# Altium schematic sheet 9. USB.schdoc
size 297 x 209 mm; Symbol: Drawing-Symbol_A4; Company: 嘉立创EDA; Version: V1.0; Page Size: A4; @Project Name: 西柚在学EtherCAT; @Update Date: 2026-07-29; @Create Date: 2026-07-29; Device: Drawing-Symbol_A4; @Board Name: HPM5E3YIVK1; @Page Name: P8; @Create Time: 01:19:22; @Page Count: 8; @Page No: 8; @Schematic Name: HPM5E3YIVK1; @Update Time: 01:19:22; @Assembly Variant: Basic; Border: 1; Title Block Position: 3; Size: A4; Width: 1170; Height: 825; Region Start: 1; X Region Count: 6; Y Region Count: 4; Blade Width: 10
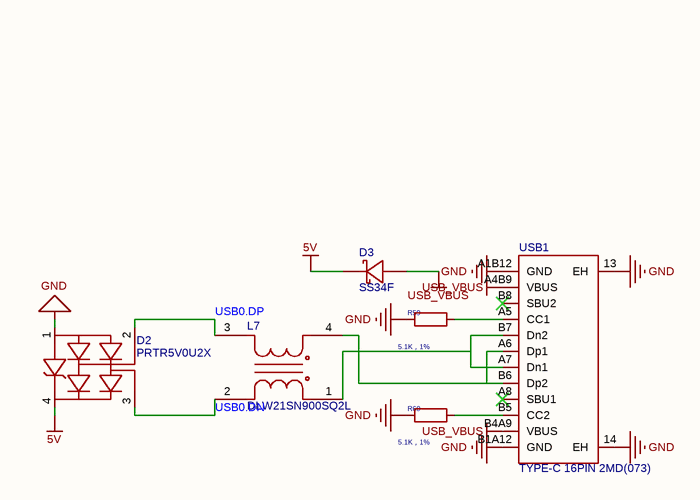
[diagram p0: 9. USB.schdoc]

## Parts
D2  PRTR5V0U2X  [SOT-143-4_L2.9-W1.3-P1.92-LS2.4-BL]
D3  SS34F  [SMAF_L3.5-W2.6-LS4.7-RD-1]
L7  DLW21SN900SQ2L  [FILTER-SMD_4P-L2.0-W1.2-BL_DLW21H]
R59  value 5.1K，1%  [02_HPM_Resistor:R_0402_1005Metric]
R60  value 5.1K，1%  [02_HPM_Resistor:R_0402_1005Metric]
USB1  TYPE-C 16PIN 2MD(073)  [USB-C-SMD_TYPE-C-16PIN-2MD-073]

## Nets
5V: D2.4 D3.1(K)
GND: D2.1 R59.1 R60.1 USB1.13(EH) USB1.14(EH) USB1.A1B12(GND) USB1.B1A12(GND)
USB_VBUS: D3.2(A) USB1.A4B9(VBUS) USB1.B4A9(VBUS)
USB0.DN: D2.3 L7.2
USB0.DP: D2.2 L7.3
NetL7_1: L7.1 USB1.A7(Dn1) USB1.B7(Dn2)
NetL7_4: L7.4 USB1.A6(Dp1) USB1.B6(Dp2)
NetR59_2: R59.2 USB1.A5(CC1)
NetR60_2: R60.2 USB1.B5(CC2)

Not connected (* = marked no-connect by the designer): USB1 A8(SBU1)* B8(SBU2)*

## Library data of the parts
D2 = PRTR5V0U2X: 极性:单向;反向截止电压(Vrwm):5V;钳位电压:10V；15V;峰值脉冲电流(Ipp):6A;峰值脉冲功率(Ppp):100W;击穿电压(VBR):6.5V;; Manufacturer: TECH PUBLIC(台舟); Symbol: PRTR5V0U2X_C2827688; AddInBom: yes; ModelId: 2837e3608ba24a5fbaabe401bacde7910819f05c4eef4c71ace90d822a990e87; ModelTransform: 114.173,93.3069,0,0,0,0,-0.003,0,0; Polarity: 单向; Reverse Stand-Off Voltage (Vrwm): 5V; Peak Pulse Current (Ipp): 6A; Peak Pulse Power Dissipation (Ppp): 100W; Voltage - Breakdown: 6.5V; Reverse Leakage Current (Ir): 80nA; Number of Channels: 三路; level of protection: IEC 61000-4-2；IEC 61000-4-4；IEC 61000-4-5; Type: ESD; Junction Capacitance: 0.8pF；0.3pF
D3 = SS34F_C18199199: 二极管配置:独立式;正向压降(Vf):550mV@3.0A;直流反向耐压(Vr):40V;整流电流:3A;; Manufacturer: R+O(宏嘉诚); AddInBom: yes; ModelId: 4caf566195a049cf809ac17c4d6419320819f05c4eef4c71ace90d822a990e87; ModelTransform: 183.0705,102.362,0,0,0,0,0,0,0; Diode Configuration: 独立式; Voltage - DC Reverse(Vr): 40V; Current - Rectified: 3A; Reverse Leakage Current (Ir): 200uA@40V; Operating Junction Temperature Range: -55℃~+125℃; Non-Repetitive Peak Forward Surge Current: 80A
L7 = DLW21SN900SQ2L: 通道数:2;阻抗@频率:90Ω@100MHz;直流电阻(DCR):-;; Manufacturer: muRata(村田); AddInBom: yes; ModelId: 2ee9896fb24849a1ae3ad995e0a10c070819f05c4eef4c71ace90d822a990e87; ModelName: SMD-4_L2.0-W1.2-H1.3; ModelTransform: 79.527,47.244,0,90,0,0,0,0,0; Number of Lines: 2; Current Rating: 330mA
R59 = 电阻0402: Model: 0402WGF1002TCE; Company: UNI-ROYAL(厚声); ki_keywords: R res resistor; ki_description: Resistor; ki_fp_filters: R_*; ID: $3I57; 3D Model: 98c88bc2b9094f218f3a3e30a70127380819f05c4eef4c71ace90d822a990e87; 3D Model Transform: 39.37,19.685,14.173200563192367,0,0,0,0,0,0; AddInBom: yes; UniqueId: 469542c170a520e3_39; ModelName: R0402_L1.0-W0.5-H0.4
R60 = 电阻0402: Model: 0402WGF1002TCE; Company: UNI-ROYAL(厚声); ki_keywords: R res resistor; ki_description: Resistor; ki_fp_filters: R_*; ID: $3I57; 3D Model: 98c88bc2b9094f218f3a3e30a70127380819f05c4eef4c71ace90d822a990e87; 3D Model Transform: 39.37,19.685,14.173200563192367,0,0,0,0,0,0; AddInBom: yes; UniqueId: 469542c170a520e3_40; ModelName: R0402_L1.0-W0.5-H0.4
USB1 = TYPE-C 16PIN 2MD(073): 连接器类型:Type-C;协议标准:-;公母:母;安装方式:卧贴;触点数量:16P;端口数量:1;额定电流 - 电源:3A;工作温度:-25℃~+85℃;; Manufacturer: SHOU HAN(首韩); AddInBom: yes; ModelId: 3a41b9ec9b654a0fad4d118405ec62900819f05c4eef4c71ace90d822a990e87; ModelName: USB-C-SMD_TYPE-C-6PIN-2MD-073; ModelTransform: 351.9678,298.4246,0,0,0,0,0,-47.244,-35.433; Gender: 母; Number of Contacts: 16P; Number of Ports: 1; Current Rating-Power: 3A; Voltage Rating: 5V; Connect-Disconnect Life: 1万次; Detection color: 黑色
